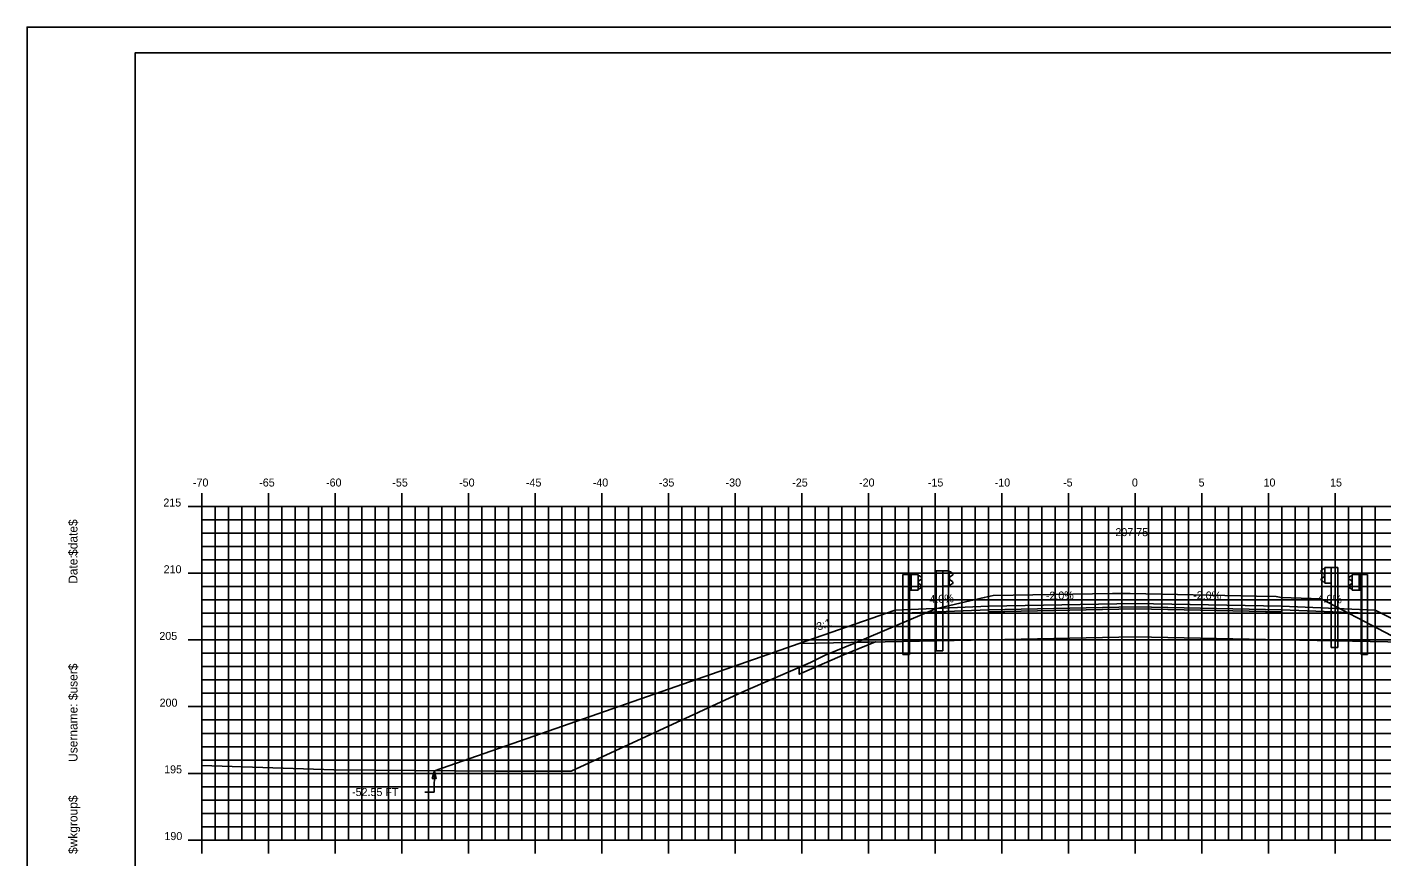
# Model space of a CAD drawing. Extents: x 1138541 to 1138711, y 608981 to 609091.
# Drawn here: x 1138541.3 to 1138642.9, y 609029.1 to 609091.3 of the extents above; entities that cross this region are included whole.
import ezdxf

# ---------------------------------------------------------------- set-up
doc = ezdxf.new("R2010")
doc.units = 0
for name, color, linetype in [('ANNOTATION', 7, 'Continuous'), ('BORDER', 7, 'Continuous'), ('D_Guardrail_Beam_Lt', 7, 'Continuous'), ('D_Guardrail_Beam_Rt', 7, 'Continuous'), ('D_Roadway_Centerline', 7, 'Continuous'), ('D_Roadway_Centerline_Text', 7, 'Continuous'), ('D_Roadway_Edge_Shoulder', 7, 'Continuous'), ('D_Roadway_Edge_TW', 7, 'Continuous'), ('D_Roadway_Pavement', 7, 'Continuous'), ('D_Roadway_SlopeLines', 7, 'Continuous'), ('D_Roadway_SubGrade', 7, 'Continuous'), ('D_Text_Standard', 7, 'Continuous'), ('H_V ANNOTATION', 7, 'Continuous'), ('MAJOR', 7, 'Continuous'), ('MINOR', 7, 'Continuous'), ('PLOT BOUNDARY', 7, 'Continuous'), ('S_Guardrail_Beam', 7, 'Continuous'), ('S_Roadway_Centerline', 7, 'Continuous'), ('SHADING', 7, 'Continuous')]:
    doc.layers.add(name, color=color, linetype=linetype)

msp = doc.modelspace()

# ---------------------------------------------------------------- linework, layer by layer
msp.add_lwpolyline([(1138571.88, 609035.54), (1138596.38, 609044.08), (1138599.25, 609045.08), (1138606.43, 609047.58), (1138606.44, 609047.58), (1138613.44, 609047.86), (1138624.44, 609048.08), (1138635.44, 609047.86), (1138642.44, 609047.58), (1138647.35, 609045.13), (1138649.35, 609044.13), (1138665.03, 609036.29)])
at = {"layer": 'BORDER'}
msp.add_lwpolyline([(1138549.44, 608984.34), (1138709.44, 608984.34), (1138709.44, 609089.34), (1138549.44, 609089.34)], close=True, dxfattribs=at)
at = {"layer": 'D_Guardrail_Beam_Lt'}
for p, q in [((1138607.01, 609050.25), (1138607.01, 609044.25)), ((1138607.48, 609050.25), (1138607.01, 609050.25)), ((1138608.16, 609050.25), (1138607.48, 609050.25)), ((1138607.48, 609050.25), (1138607.48, 609049.08)), ((1138607.54, 609050.25), (1138607.54, 609049.08)), ((1138607.64, 609050.25), (1138607.64, 609049.08)), ((1138608.16, 609049.08), (1138608.16, 609050.25)), ((1138608.16, 609050.16), (1138608.24, 609050.15)), ((1138608.4, 609049.9), (1138608.2, 609049.76)), ((1138608.25, 609050.14), (1138608.4, 609050.04)), ((1138640.62, 609050.14), (1138640.47, 609050.04)), ((1138640.47, 609049.9), (1138640.67, 609049.76)), ((1138640.71, 609050.16), (1138640.63, 609050.15)), ((1138607.48, 609049.08), (1138608.16, 609049.08)), ((1138607.5, 609044.25), (1138607.5, 609049.08)), ((1138608.24, 609049.18), (1138608.16, 609049.16)), ((1138608.17, 609049.7), (1138608.17, 609049.63)), ((1138608.2, 609049.56), (1138608.4, 609049.43)), ((1138608.4, 609049.28), (1138608.25, 609049.18)), ((1138640.67, 609049.56), (1138640.47, 609049.43)), ((1138640.47, 609049.28), (1138640.62, 609049.18)), ((1138640.63, 609049.18), (1138640.71, 609049.16)), ((1138640.7, 609049.7), (1138640.7, 609049.63)), ((1138607.5, 609044.25), (1138607.01, 609044.25))]:
    msp.add_line(p, q, dxfattribs=at)
for centre, major_axis, start_param, end_param in [((1138608.23, 609050.11), (0.0417, 0), 0.959931, 1.376053), ((1138608.35, 609049.97), (0.0877, 0), 5.323254, 7.243116), ((1138640.52, 609049.97), (-0.0877, 0), 5.323254, 7.243116), ((1138640.64, 609050.11), (-0.0417, 0), 4.907132, 5.323254), ((1138608.25, 609049.7), (-0.0789, 0), 5.323254, 6.283185), ((1138608.25, 609049.63), (-0.0789, 0), 6.283185, 7.243116), ((1138608.23, 609049.22), (0.0417, 0), 4.907132, 5.323254), ((1138608.35, 609049.36), (0.0877, 0), 5.323254, 7.243116), ((1138640.52, 609049.36), (-0.0877, 0), 5.323254, 7.243116), ((1138640.64, 609049.22), (-0.0417, 0), 0.959931, 1.376053), ((1138640.62, 609049.7), (0.0789, 0), 0, 0.959931), ((1138640.62, 609049.63), (0.0789, 0), 5.323254, 6.283185)]:
    msp.add_ellipse(centre, major_axis=major_axis, ratio=0.995501, start_param=start_param, end_param=end_param, dxfattribs=at)
at = {"layer": 'D_Guardrail_Beam_Rt'}
for p, q in [((1138640.71, 609050.25), (1138641.39, 609050.25)), ((1138640.71, 609049.08), (1138640.71, 609050.25)), ((1138641.23, 609050.25), (1138641.23, 609049.08)), ((1138641.33, 609050.25), (1138641.33, 609049.08)), ((1138641.39, 609050.25), (1138641.86, 609050.25)), ((1138641.39, 609050.25), (1138641.39, 609049.08)), ((1138641.86, 609050.25), (1138641.86, 609044.25)), ((1138641.39, 609049.08), (1138640.71, 609049.08)), ((1138641.37, 609044.25), (1138641.37, 609049.08)), ((1138641.37, 609044.25), (1138641.86, 609044.25))]:
    msp.add_line(p, q, dxfattribs=at)
at = {"layer": 'D_Roadway_Edge_Shoulder'}
for points in [[(1138613.44, 609047.86), (1138606.44, 609047.58), (1138606.44, 609047.33), (1138613.44, 609047.61)], [(1138635.44, 609047.86), (1138642.44, 609047.58), (1138642.44, 609047.33), (1138635.44, 609047.61)]]:
    msp.add_lwpolyline(points, close=True, dxfattribs=at)
at = {"layer": 'D_Roadway_Edge_TW'}
msp.add_lwpolyline([(1138613.44, 609047.61), (1138613.44, 609047.86), (1138624.44, 609048.08), (1138635.44, 609047.86), (1138635.44, 609047.61), (1138624.44, 609047.83)], close=True, dxfattribs=at)
at = {"layer": 'D_Roadway_Pavement'}
msp.add_lwpolyline([(1138613.44, 609047.45), (1138613.44, 609047.61), (1138624.44, 609047.83), (1138635.44, 609047.61), (1138635.44, 609047.45), (1138624.44, 609047.67)], close=True, dxfattribs=at)
at = {"layer": 'D_Roadway_SlopeLines'}
for points in [[(1138599.25, 609045.08), (1138596.38, 609044.08)], [(1138599.25, 609043.27), (1138599.25, 609042.77), (1138600.34, 609043.26), (1138602.5, 609044.21), (1138604.96, 609045.19)], [(1138596.38, 609044.08), (1138571.88, 609035.54)]]:
    msp.add_lwpolyline(points, dxfattribs=at)
at = {"layer": 'D_Roadway_SubGrade'}
for points in [[(1138613.44, 609047.45), (1138613.44, 609047.61), (1138606.44, 609047.33), (1138606.44, 609047.58), (1138606.43, 609047.58), (1138599.25, 609045.08), (1138613.44, 609045.36)], [(1138613.44, 609045.36), (1138613.44, 609047.45), (1138624.44, 609047.67), (1138635.44, 609047.45), (1138635.44, 609045.36), (1138624.44, 609045.58)], [(1138635.44, 609047.45), (1138635.44, 609047.61), (1138642.44, 609047.33), (1138642.44, 609047.58), (1138642.44, 609047.58), (1138647.35, 609045.13), (1138635.44, 609045.36)]]:
    msp.add_lwpolyline(points, close=True, dxfattribs=at)
at = {"layer": 'D_Text_Standard'}
msp.add_lwpolyline([(1138571.88, 609035.54), (1138571.86, 609033.94), (1138571.18, 609033.94)], dxfattribs=at)
msp.add_lwpolyline([(1138571.88, 609035.54), (1138572.02, 609034.96), (1138571.73, 609034.96)], close=True, dxfattribs=at)
at = {"layer": 'MAJOR'}
for p, q in [((1138554.44, 609056.34), (1138554.44, 609055.34)), ((1138559.44, 609056.34), (1138559.44, 609055.34)), ((1138564.44, 609056.34), (1138564.44, 609055.34)), ((1138569.44, 609056.34), (1138569.44, 609055.34)), ((1138574.44, 609056.34), (1138574.44, 609055.34)), ((1138579.44, 609056.34), (1138579.44, 609055.34)), ((1138584.44, 609056.34), (1138584.44, 609055.34)), ((1138589.44, 609056.34), (1138589.44, 609055.34)), ((1138594.44, 609056.34), (1138594.44, 609055.34)), ((1138599.44, 609056.34), (1138599.44, 609055.34)), ((1138604.44, 609056.34), (1138604.44, 609055.34)), ((1138609.44, 609056.34), (1138609.44, 609055.34)), ((1138614.44, 609056.34), (1138614.44, 609055.34)), ((1138619.44, 609056.34), (1138619.44, 609055.34)), ((1138624.44, 609056.34), (1138624.44, 609055.34)), ((1138629.44, 609056.34), (1138629.44, 609055.34)), ((1138634.44, 609056.34), (1138634.44, 609055.34)), ((1138639.44, 609056.34), (1138639.44, 609055.34)), ((1138553.43, 609055.34), (1138554.44, 609055.34)), ((1138554.44, 609055.34), (1138694.44, 609055.34)), ((1138554.44, 609030.34), (1138554.44, 609055.34)), ((1138554.44, 609030.34), (1138554.44, 609055.34)), ((1138554.44, 609055.34), (1138694.44, 609055.34)), ((1138559.44, 609030.34), (1138559.44, 609055.34)), ((1138564.44, 609030.34), (1138564.44, 609055.34)), ((1138569.44, 609030.34), (1138569.44, 609055.34)), ((1138574.44, 609030.34), (1138574.44, 609055.34)), ((1138579.44, 609030.34), (1138579.44, 609055.34)), ((1138584.44, 609030.34), (1138584.44, 609055.34)), ((1138589.44, 609030.34), (1138589.44, 609055.34)), ((1138594.44, 609030.34), (1138594.44, 609055.34)), ((1138599.44, 609030.34), (1138599.44, 609055.34)), ((1138604.44, 609030.34), (1138604.44, 609055.34)), ((1138609.44, 609030.34), (1138609.44, 609055.34)), ((1138614.44, 609030.34), (1138614.44, 609055.34)), ((1138619.44, 609030.34), (1138619.44, 609055.34)), ((1138624.44, 609030.34), (1138624.44, 609055.34)), ((1138629.44, 609030.34), (1138629.44, 609055.34)), ((1138634.44, 609030.34), (1138634.44, 609055.34)), ((1138639.44, 609030.34), (1138639.44, 609055.34)), ((1138553.43, 609050.34), (1138554.44, 609050.34)), ((1138554.44, 609050.34), (1138694.44, 609050.34)), ((1138553.43, 609045.34), (1138554.44, 609045.34)), ((1138554.44, 609045.34), (1138694.44, 609045.34)), ((1138553.43, 609040.34), (1138554.44, 609040.34)), ((1138554.44, 609040.34), (1138694.44, 609040.34)), ((1138553.43, 609035.34), (1138554.44, 609035.34)), ((1138554.44, 609035.34), (1138694.44, 609035.34)), ((1138553.43, 609030.34), (1138554.44, 609030.34)), ((1138554.44, 609030.34), (1138694.44, 609030.34)), ((1138554.44, 609030.34), (1138694.44, 609030.34)), ((1138554.44, 609029.33), (1138554.44, 609030.34)), ((1138559.44, 609029.33), (1138559.44, 609030.34)), ((1138564.44, 609029.33), (1138564.44, 609030.34)), ((1138569.44, 609029.33), (1138569.44, 609030.34)), ((1138574.44, 609029.33), (1138574.44, 609030.34)), ((1138579.44, 609029.33), (1138579.44, 609030.34)), ((1138584.44, 609029.33), (1138584.44, 609030.34)), ((1138589.44, 609029.33), (1138589.44, 609030.34)), ((1138594.44, 609029.33), (1138594.44, 609030.34)), ((1138599.44, 609029.33), (1138599.44, 609030.34)), ((1138604.44, 609029.33), (1138604.44, 609030.34)), ((1138609.44, 609029.33), (1138609.44, 609030.34)), ((1138614.44, 609029.33), (1138614.44, 609030.34)), ((1138619.44, 609029.33), (1138619.44, 609030.34)), ((1138624.44, 609029.33), (1138624.44, 609030.34)), ((1138629.44, 609029.33), (1138629.44, 609030.34)), ((1138634.44, 609029.33), (1138634.44, 609030.34)), ((1138639.44, 609029.33), (1138639.44, 609030.34))]:
    msp.add_line(p, q, dxfattribs=at)
at = {"layer": 'MINOR'}
for p, q in [((1138555.44, 609030.34), (1138555.44, 609055.34)), ((1138556.44, 609030.34), (1138556.44, 609055.34)), ((1138557.44, 609030.34), (1138557.44, 609055.34)), ((1138558.44, 609030.34), (1138558.44, 609055.34)), ((1138560.44, 609030.34), (1138560.44, 609055.34)), ((1138561.44, 609030.34), (1138561.44, 609055.34)), ((1138562.44, 609030.34), (1138562.44, 609055.34)), ((1138563.44, 609030.34), (1138563.44, 609055.34)), ((1138565.44, 609030.34), (1138565.44, 609055.34)), ((1138566.44, 609030.34), (1138566.44, 609055.34)), ((1138567.44, 609030.34), (1138567.44, 609055.34)), ((1138568.44, 609030.34), (1138568.44, 609055.34)), ((1138570.44, 609030.34), (1138570.44, 609055.34)), ((1138571.44, 609030.34), (1138571.44, 609055.34)), ((1138572.44, 609030.34), (1138572.44, 609055.34)), ((1138573.44, 609030.34), (1138573.44, 609055.34)), ((1138575.44, 609030.34), (1138575.44, 609055.34)), ((1138576.44, 609030.34), (1138576.44, 609055.34)), ((1138577.44, 609030.34), (1138577.44, 609055.34)), ((1138578.44, 609030.34), (1138578.44, 609055.34)), ((1138580.44, 609030.34), (1138580.44, 609055.34)), ((1138581.44, 609030.34), (1138581.44, 609055.34)), ((1138582.44, 609030.34), (1138582.44, 609055.34)), ((1138583.44, 609030.34), (1138583.44, 609055.34)), ((1138585.44, 609030.34), (1138585.44, 609055.34)), ((1138586.44, 609030.34), (1138586.44, 609055.34)), ((1138587.44, 609030.34), (1138587.44, 609055.34)), ((1138588.44, 609030.34), (1138588.44, 609055.34)), ((1138590.44, 609030.34), (1138590.44, 609055.34)), ((1138591.44, 609030.34), (1138591.44, 609055.34)), ((1138592.44, 609030.34), (1138592.44, 609055.34)), ((1138593.44, 609030.34), (1138593.44, 609055.34)), ((1138595.44, 609030.34), (1138595.44, 609055.34)), ((1138596.44, 609030.34), (1138596.44, 609055.34)), ((1138597.44, 609030.34), (1138597.44, 609055.34)), ((1138598.44, 609030.34), (1138598.44, 609055.34)), ((1138600.44, 609030.34), (1138600.44, 609055.34)), ((1138601.44, 609030.34), (1138601.44, 609055.34)), ((1138602.44, 609030.34), (1138602.44, 609055.34)), ((1138603.44, 609030.34), (1138603.44, 609055.34)), ((1138605.44, 609030.34), (1138605.44, 609055.34)), ((1138606.44, 609030.34), (1138606.44, 609055.34)), ((1138607.44, 609030.34), (1138607.44, 609055.34)), ((1138608.44, 609030.34), (1138608.44, 609055.34)), ((1138610.44, 609030.34), (1138610.44, 609055.34)), ((1138611.44, 609030.34), (1138611.44, 609055.34)), ((1138612.44, 609030.34), (1138612.44, 609055.34)), ((1138613.44, 609030.34), (1138613.44, 609055.34)), ((1138615.44, 609030.34), (1138615.44, 609055.34)), ((1138616.44, 609030.34), (1138616.44, 609055.34)), ((1138617.44, 609030.34), (1138617.44, 609055.34)), ((1138618.44, 609030.34), (1138618.44, 609055.34)), ((1138620.44, 609030.34), (1138620.44, 609055.34)), ((1138621.44, 609030.34), (1138621.44, 609055.34)), ((1138622.44, 609030.34), (1138622.44, 609055.34)), ((1138623.44, 609030.34), (1138623.44, 609055.34)), ((1138625.44, 609030.34), (1138625.44, 609055.34)), ((1138626.44, 609030.34), (1138626.44, 609055.34)), ((1138627.44, 609030.34), (1138627.44, 609055.34)), ((1138628.44, 609030.34), (1138628.44, 609055.34)), ((1138630.44, 609030.34), (1138630.44, 609055.34)), ((1138631.44, 609030.34), (1138631.44, 609055.34)), ((1138632.44, 609030.34), (1138632.44, 609055.34)), ((1138633.44, 609030.34), (1138633.44, 609055.34)), ((1138635.44, 609030.34), (1138635.44, 609055.34)), ((1138636.44, 609030.34), (1138636.44, 609055.34)), ((1138637.44, 609030.34), (1138637.44, 609055.34)), ((1138638.44, 609030.34), (1138638.44, 609055.34)), ((1138640.44, 609030.34), (1138640.44, 609055.34)), ((1138641.44, 609030.34), (1138641.44, 609055.34)), ((1138642.44, 609030.34), (1138642.44, 609055.34)), ((1138554.44, 609054.34), (1138694.44, 609054.34)), ((1138554.44, 609054.34), (1138555.44, 609054.34)), ((1138554.44, 609053.34), (1138694.44, 609053.34)), ((1138554.44, 609053.34), (1138555.44, 609053.34)), ((1138554.44, 609052.34), (1138694.44, 609052.34)), ((1138554.44, 609052.34), (1138555.44, 609052.34)), ((1138554.44, 609051.34), (1138694.44, 609051.34)), ((1138554.44, 609051.34), (1138555.44, 609051.34)), ((1138554.44, 609049.34), (1138694.44, 609049.34)), ((1138554.44, 609049.34), (1138555.44, 609049.34)), ((1138554.44, 609048.34), (1138694.44, 609048.34)), ((1138554.44, 609048.34), (1138555.44, 609048.34)), ((1138554.44, 609047.34), (1138694.44, 609047.34)), ((1138554.44, 609047.34), (1138555.44, 609047.34)), ((1138554.44, 609046.34), (1138694.44, 609046.34)), ((1138554.44, 609046.34), (1138555.44, 609046.34)), ((1138554.44, 609044.34), (1138694.44, 609044.34)), ((1138554.44, 609044.34), (1138555.44, 609044.34)), ((1138554.44, 609043.34), (1138694.44, 609043.34)), ((1138554.44, 609043.34), (1138555.44, 609043.34)), ((1138554.44, 609042.34), (1138694.44, 609042.34)), ((1138554.44, 609042.34), (1138555.44, 609042.34)), ((1138554.44, 609041.34), (1138694.44, 609041.34)), ((1138554.44, 609041.34), (1138555.44, 609041.34)), ((1138554.44, 609039.34), (1138694.44, 609039.34)), ((1138554.44, 609039.34), (1138555.44, 609039.34)), ((1138554.44, 609038.34), (1138694.44, 609038.34)), ((1138554.44, 609038.34), (1138555.44, 609038.34)), ((1138554.44, 609037.34), (1138694.44, 609037.34)), ((1138554.44, 609037.34), (1138555.44, 609037.34)), ((1138554.44, 609036.34), (1138694.44, 609036.34)), ((1138554.44, 609036.34), (1138555.44, 609036.34)), ((1138554.44, 609034.34), (1138694.44, 609034.34)), ((1138554.44, 609034.34), (1138555.44, 609034.34)), ((1138554.44, 609033.34), (1138694.44, 609033.34)), ((1138554.44, 609033.34), (1138555.44, 609033.34)), ((1138554.44, 609032.34), (1138694.44, 609032.34)), ((1138554.44, 609032.34), (1138555.44, 609032.34)), ((1138554.44, 609031.34), (1138694.44, 609031.34)), ((1138554.44, 609031.34), (1138555.44, 609031.34))]:
    msp.add_line(p, q, dxfattribs=at)
at = {"layer": 'PLOT BOUNDARY'}
msp.add_lwpolyline([(1138541.34, 608981.28), (1138711.34, 608981.28), (1138711.34, 609091.28), (1138541.34, 609091.28)], close=True, dxfattribs=at)
at = {"layer": 'S_Guardrail_Beam'}
for p, q in [((1138609.51, 609050.53), (1138609.51, 609044.53)), ((1138610, 609050.53), (1138609.51, 609050.53)), ((1138610.49, 609050.53), (1138610, 609050.53)), ((1138610, 609050.53), (1138610, 609049.37)), ((1138610.49, 609049.37), (1138610.49, 609050.53)), ((1138610.49, 609050.46), (1138610.58, 609050.45)), ((1138610.51, 609050), (1138610.51, 609049.91)), ((1138610.74, 609050.2), (1138610.54, 609050.06)), ((1138610.59, 609050.44), (1138610.74, 609050.34)), ((1138638.55, 609050.67), (1138638.41, 609050.57)), ((1138638.41, 609050.43), (1138638.6, 609050.29)), ((1138638.6, 609050.07), (1138638.41, 609049.94)), ((1138638.65, 609050.69), (1138638.57, 609050.68)), ((1138638.64, 609050.23), (1138638.64, 609050.14)), ((1138638.65, 609050.77), (1138639.14, 609050.77)), ((1138638.65, 609049.6), (1138638.65, 609050.77)), ((1138639.14, 609050.77), (1138639.63, 609050.77)), ((1138639.14, 609050.77), (1138639.14, 609049.6)), ((1138639.63, 609050.77), (1138639.63, 609044.77)), ((1138610, 609044.53), (1138610, 609049.37)), ((1138610, 609049.37), (1138610.49, 609049.37)), ((1138610.58, 609049.46), (1138610.49, 609049.44)), ((1138610.54, 609049.84), (1138610.74, 609049.71)), ((1138610.74, 609049.56), (1138610.59, 609049.46)), ((1138638.41, 609049.79), (1138638.55, 609049.69)), ((1138638.57, 609049.69), (1138638.65, 609049.67)), ((1138639.14, 609049.6), (1138638.65, 609049.6)), ((1138639.14, 609044.77), (1138639.14, 609049.6)), ((1138610, 609044.53), (1138609.51, 609044.53)), ((1138639.14, 609044.77), (1138639.63, 609044.77))]:
    msp.add_line(p, q, dxfattribs=at)
for centre, major_axis, start_param, end_param in [((1138610.59, 609050), (-0.0789, 0), 5.323254, 6.283185), ((1138610.59, 609049.91), (-0.0789, 0), 6.283185, 7.243116), ((1138610.57, 609050.41), (0.0417, 0), 0.959931, 1.396263), ((1138610.69, 609050.27), (0.0877, 0), 5.323254, 7.243116), ((1138638.46, 609050.5), (-0.0877, 0), 5.323254, 7.243116), ((1138638.46, 609049.87), (-0.0877, 0), 5.323254, 7.243116), ((1138638.57, 609050.64), (-0.0417, 0), 4.886922, 5.323254), ((1138638.56, 609050.23), (0.0789, 0), 0, 0.959931), ((1138638.56, 609050.14), (0.0789, 0), 5.323254, 6.283185), ((1138610.57, 609049.5), (0.0417, 0), 4.886922, 5.323254), ((1138610.69, 609049.63), (0.0877, 0), 5.323254, 7.243116), ((1138638.57, 609049.73), (-0.0417, 0), 0.959931, 1.396263)]:
    msp.add_ellipse(centre, major_axis=major_axis, ratio=0.995501, start_param=start_param, end_param=end_param, dxfattribs=at)
at = {"layer": 'S_Roadway_Centerline'}
msp.add_lwpolyline([(1138554.44, 609035.94), (1138564.35, 609035.61), (1138576.51, 609035.5), (1138582.15, 609035.51), (1138595.01, 609041.44), (1138600.1, 609043.64), (1138601.18, 609044.21), (1138603.45, 609045.12), (1138609.46, 609047.66), (1138613.12, 609048.52), (1138613.79, 609048.68), (1138622.74, 609048.81), (1138624.07, 609048.82), (1138633.52, 609048.62), (1138635, 609048.59), (1138635.37, 609048.52), (1138638.38, 609048.43), (1138647.92, 609043.42), (1138661.81, 609036.36), (1138662.48, 609036.35), (1138687.3, 609035.72), (1138694.44, 609035.52)], dxfattribs=at)
at = {"layer": 'SHADING'}
msp.add_line((1138604.96, 609045.19), (1138603.55, 609045.17), dxfattribs=at)
for points in [[(1138599.25, 609043.27), (1138599.25, 609042.77), (1138600.34, 609043.26), (1138602.5, 609044.21), (1138604.96, 609045.19)], [(1138603.55, 609045.17), (1138603.45, 609045.12), (1138601.18, 609044.21), (1138600.1, 609043.64), (1138599.25, 609043.27)]]:
    msp.add_lwpolyline(points, dxfattribs=at)

# ---------------------------------------------------------------- texts
at = {"layer": 'ANNOTATION'}
for s, rotation, p in [('-2.0%', 1.1458, (1138617.74, 609048.35)), ('-2.0%', 358.8542, (1138628.78, 609048.4)), ('-4.0%', 2.2906, (1138608.75, 609048.08)), ('-4.0%', 357.7094, (1138637.83, 609048.17)), ('-3:1', 19.2101, (1138600.41, 609045.94))]:
    msp.add_text(s, height=0.6, rotation=rotation, dxfattribs=at).set_placement(p)
at = {"layer": 'BORDER'}
for s, p in [('$date$', (1138545.12, 609051.64)), ('Date:', (1138545.12, 609049.55)), ('$user$', (1138545.12, 609040.83)), ('Username:', (1138545.12, 609036.2)), ('$wkgroup$', (1138545.12, 609029.3))]:
    msp.add_text(s, height=0.67, rotation=90, dxfattribs=at).set_placement(p)
at = {"layer": 'D_Roadway_Centerline'}
for s, p in [('C', (1138624.43, 609048.08)), ('L', (1138624.44, 609048.08))]:
    msp.add_text(s, height=0.0146, dxfattribs=at).set_placement(p)
at = {"layer": 'D_Roadway_Centerline_Text'}
msp.add_text('207.75', height=0.6, dxfattribs=at).set_placement((1138622.95, 609053.12))
at = {"layer": 'D_Text_Standard'}
msp.add_text('-52.55 FT', height=0.6, dxfattribs=at).set_placement((1138565.71, 609033.64))
at = {"layer": 'H_V ANNOTATION'}
for s, p in [('-70', (1138553.78, 609056.84)), ('-65', (1138558.75, 609056.84)), ('-60', (1138563.76, 609056.84)), ('-55', (1138568.73, 609056.84)), ('-50', (1138573.74, 609056.84)), ('-45', (1138578.75, 609056.84)), ('-40', (1138583.76, 609056.84)), ('-35', (1138588.72, 609056.84)), ('-30', (1138593.72, 609056.84)), ('-25', (1138598.72, 609056.84)), ('-20', (1138603.73, 609056.84)), ('-15', (1138608.89, 609056.84)), ('-10', (1138613.9, 609056.84)), ('-5', (1138619.03, 609056.84)), ('0', (1138624.19, 609056.84)), ('5', (1138629.19, 609056.84)), ('10', (1138634.06, 609056.84)), ('15', (1138639.05, 609056.84)), ('215', (1138551.56, 609055.34)), ('210', (1138551.58, 609050.34)), ('205', (1138551.26, 609045.34)), ('200', (1138551.28, 609040.34)), ('195', (1138551.62, 609035.34)), ('190', (1138551.64, 609030.34))]:
    msp.add_text(s, height=0.6, dxfattribs=at).set_placement(p)
at = {"layer": 'MAJOR'}
msp.add_text('-', height=0.006, dxfattribs=at).set_placement((1138554.43, 609030.34))
at = {"layer": 'S_Roadway_Centerline'}
for s, p in [('C', (1138624.06, 609048.82)), ('L', (1138624.06, 609048.81))]:
    msp.add_text(s, height=0.0146, dxfattribs=at).set_placement(p)

doc.saveas('drawing.dxf')
